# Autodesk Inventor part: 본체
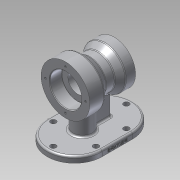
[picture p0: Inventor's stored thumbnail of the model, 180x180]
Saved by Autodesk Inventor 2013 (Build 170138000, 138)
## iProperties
Created: 2020-01
Part Number: 본체
Material: 알루미늄 6061
Document SubType Name: Modeling
Designer: Administrator
Mass: 941.582 g
Surface Area: 654.888 cm^2
Volume: 347.447 cm^3
Density: 2.71 g/cm^3
Author: Administrator
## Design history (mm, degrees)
sketch "스케치1"
  geometry: L1 (0, 40)-(0, -40); L2 (0, 40)-(26, 40); L3 (40, 40)-(40, 16); L4 (40, 16)-(27.5, 1.103); L5 (27.5, 1.103)-(27.5, -13.289); L6 (27.5, -13.289)-(35, -24); L7 (35, -24)-(35, -40); L8 (35, -40)-(20, -40); L9 (26, 40)-(26, 20); L10 (26, 20)-(16, 20); L11 (16, 20)-(16, -23); L12 (16, -23)-(20, -23); L13 (20, -23)-(20, -40); L14 (26, 40)-(40, 40); L15 (20, -40)-(0, -40); 1 further point
  constraints: 30 end point, 9 perpendicular, 4 parallel, 2 horizontal, 1 midpoint, 1 vertical
  dimensions: "d0" = 80 distance of L1.start L1.end; "d2" = 40 distance of point (0, 0) L1.start; "d3" = 80 diameter of L3 L1; "d4" = 70 diameter of L7 L1; "d5" = 55 diameter of L5 L1; "d6" = 24 distance of L3.start L3.end; "d7" = 16 distance of L6.end L7.end; "d8" = 40 deg angle of L5 L4; "d9" = 35 deg angle of L5 L6; "d11" = 52 diameter of L9 L1; "d12" = 40 diameter of L13 L1; "d13" = 32 diameter of L11 L1; "d14" = 20 distance of L2.end L9.end; "d15" = 17 distance of L12.end L8.end
revolve "회전1" sketch "스케치1" stored, may be unused: angle "d16" = 90 deg
fillet "모깎기1" dims "d17" = 3
fillet "모깎기2" dims "d18" = 0.3
sketch "스케치2"
  geometry: C1 r 40 at (0, 0) reference; 1 further point
  constraints: 1 vertical alignment
  dimensions: "d19" = 33 distance of C1.centre point (0, 33)
hole "구멍1" sketch "스케치2" at (0, 33) diameter "d20" = 3.242; stored, may be unused: countersink angle "d24" = 90 deg, drill point angle "d26" = 118 deg; dims "d21" = 9, "d22" = 4, "d23" = 2, "d25" = 11
sketch "스케치3"
  geometry: C1 r 20 at (0, 0) reference; 1 further point
  constraints: 1 vertical alignment
  dimensions: "d27" = 27.5 distance of C1.centre point (0, 27.5)
hole "구멍2" sketch "스케치3" at (0, 27.5) diameter "d28" = 3.242; stored, may be unused: countersink angle "d32" = 90 deg, drill point angle "d34" = 118 deg; dims "d29" = 9, "d30" = 4, "d31" = 2, "d33" = 11
sketch "스케치4"
  geometry: L1 (-70, 70)-(-80, 70); L2 (-80, 70)-(-80, -70); L3 (-80, -70)-(-70, -70); L4 (-70, -70)-(-70, 70); L5 (-26, 40)-(26, 40) reference; 1 further point
  constraints: 8 end point, 2 parallel, 1 horizontal, 1 perpendicular
  dimensions: "d38" = 10 distance of L2.end L3.end; "d40" = 80 distance from line of L2 point (0, 0); "d41" = 30 distance between parallel lines of L1 L5; "d42" = 140 distance of L1.end L2.end
extrude "돌출1" join sketch "스케치4" stored distance "d43" = 90; taper "d44" = 0 deg
fillet "모깎기3" dims "d45" = 45
fillet "모깎기4" dims "d46" = 3
sketch "스케치5"
  geometry: L1 (42, 50)-(42, 0) reference; L2 (0, 25)-(-18.617, 25); A1 r 42 centre (0, 0) between (-42, 0) and (42, 0) reference; 6 further points
  constraints: 3 symmetric about line, 2 end point, 2 horizontal alignment, 1 perpendicular, 1 vertical alignment
  dimensions: "d47" = 35 distance of A1.centre point (0, -35); "d48" = 70 distance of point (-35, 0) point (35, 0); "d49" = 35 distance of A1.centre point (-35, 0)
hole "구멍3" sketch "스케치5" at (0, -35), (-35, 0), (35, 0), (35, 50), (0, 85), (-35, 50) diameter "d50" = 9; stored, may be unused: countersink angle "d54" = 90 deg, drill point angle "d56" = 118 deg; dims "d51" = 9, "d52" = 4, "d53" = 2, "d55" = 11
sketch "스케치7" dims "d58" = 32
  geometry: L1 (-5, 28.199)-(5, 28.199); L2 (5, 28.199)-(5, 55); L3 (5, 55)-(-5, 55); L4 (-5, 55)-(-5, 28.199); L5 (35, 65)-(-35, 65) reference; A1 r 42 centre (0, 0) between (-42, 0) and (42, 0) reference; A2 r 42 centre (0, 50) between (42, 50) and (-42, 50) reference; 3 further points
  constraints: 8 end point, 2 parallel, 2 vertical alignment, 1 horizontal, 1 midpoint, 1 perpendicular, 3 other
  dimensions: "d57" = 13 distance of point (0, 13) A1.centre; "d60" = 10 distance between parallel lines of L3 L5; "d61" = 10 distance of L2.end L3.end
extrude "돌출2" join sketch "스케치7" stored distance "d62" = 90; taper "d63" = 0 deg
fillet "모깎기5" dims "d64" = 3
fillet "모깎기6" dims "d65" = 3
sketch "스케치8"
  geometry: L1 (-25, -80)-(25, -80) reference; L2 (-70, -73)-(-70, -80) reference; 2 further points
  constraints: 1 other
  dimensions: "d66" = 70 distance from line of point (0, -76) L2; "d67" = 4 distance from line of point (0, -76) L1
feature "엠보싱1" sketch "스케치8" dims "d0" = 80, "d2" = 40, "d3" = 80, "d4" = 70, "d5" = 55, "d6" = 24, "d7" = 16, "d8" = 40 deg, "d9" = 35 deg, "d11" = 52, "d12" = 40, "d13" = 32, "d14" = 20, "d15" = 17, "d68" = 0.5, "d69" = 0
chamfer "모따기1" distance "d70" = 1; stored, may be unused: second distance "d71" = 2, angle "d72" = 45 deg
node "솔리드1"
pattern_circular "원형 패턴1" dims angle "d36" = 360 deg
